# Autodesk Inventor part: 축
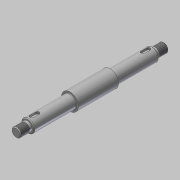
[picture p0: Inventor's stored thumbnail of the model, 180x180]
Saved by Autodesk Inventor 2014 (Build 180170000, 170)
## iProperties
Created: 2018-11
Part Number: 축
Material: 강철, 연강
Document SubType Name: Modeling
Designer: mduedu
Density: 1 g/cm^3
Appearance: 강철
Author: mduedu
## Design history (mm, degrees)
sketch "스케치1"
  geometry: L1 (-26, 0)-(26, 0); L2 (26, 0)-(26, 11); L3 (26, 11)-(-26, 11); L4 (-26, 11)-(-26, 0); L5 (-26, 0)-(-81, 0); L6 (-81, 0)-(-81, 8.5); L7 (-81, 8.5)-(-26, 8.5); L8 (-26, 8.5)-(-26, 0); L9 (-81, 0)-(-96, 0); L10 (-96, 0)-(-96, 6); L11 (-96, 6)-(-81, 6); L12 (-81, 6)-(-81, 0); L13 (0, 0)-(0, 11); L14 (26, 0)-(81, 0); L15 (81, 0)-(81, 8.5); L16 (81, 8.5)-(26, 8.5); L17 (26, 8.5)-(26, 0); L18 (81, 0)-(96, 0); L19 (96, 0)-(96, 6); L20 (96, 6)-(81, 6); L21 (81, 6)-(81, 0); 1 further point
  constraints: 42 end point, 6 parallel, 6 symmetric about line, 3 horizontal, 3 perpendicular, 2 midpoint, 1 coincident
  dimensions: "d0" = 22 diameter of L3 L1; "d2" = 17 diameter of L7 L5; "d3" = 12 diameter of L11 L9; "d4" = 52 distance of L2.end L3.end; "d5" = 55 distance of L6.end L7.end; "d6" = 192 distance between parallel lines of L19 L10
revolve "회전1" sketch "스케치1" stored, may be unused: angle "d7" = 90 deg
fillet "모깎기1" dims "d8" = 0.6
node "작업 평면1"
sketch "스케치2" dims "d11" = 12
  geometry: L1 (15, 2.5)-(22, 2.5); L2 (22, 2.5)-(22, -2.5); L3 (22, -2.5)-(15, -2.5); L4 (15, -2.5)-(15, 2.5); L5 (27.5, 8.5)-(27.5, -8.5) reference; 3 further points
  constraints: 8 end point, 2 midpoint, 2 parallel, 2 vertical alignment, 1 horizontal, 1 horizontal alignment, 1 perpendicular, 4 other
  dimensions: "d9" = 3 dimension on L5; "d10" = 5 distance between parallel lines of L3 L1
extrude "돌출1" cut sketch "스케치2" distance "d12" = 3; taper "d13" = 0 deg
chamfer "모따기1" distance "d14" = 1; stored, may be unused: second distance "d15" = 2, angle "d16" = 45 deg
feature "스레드1" dims "d17" = 12, "d18" = 0
feature "스레드2" dims "d19" = 12, "d20" = 0
chamfer "모따기2" distance "d21" = 1; stored, may be unused: second distance "d22" = 2, angle "d23" = 45 deg
node "솔리드1"
mirror "대칭1"
